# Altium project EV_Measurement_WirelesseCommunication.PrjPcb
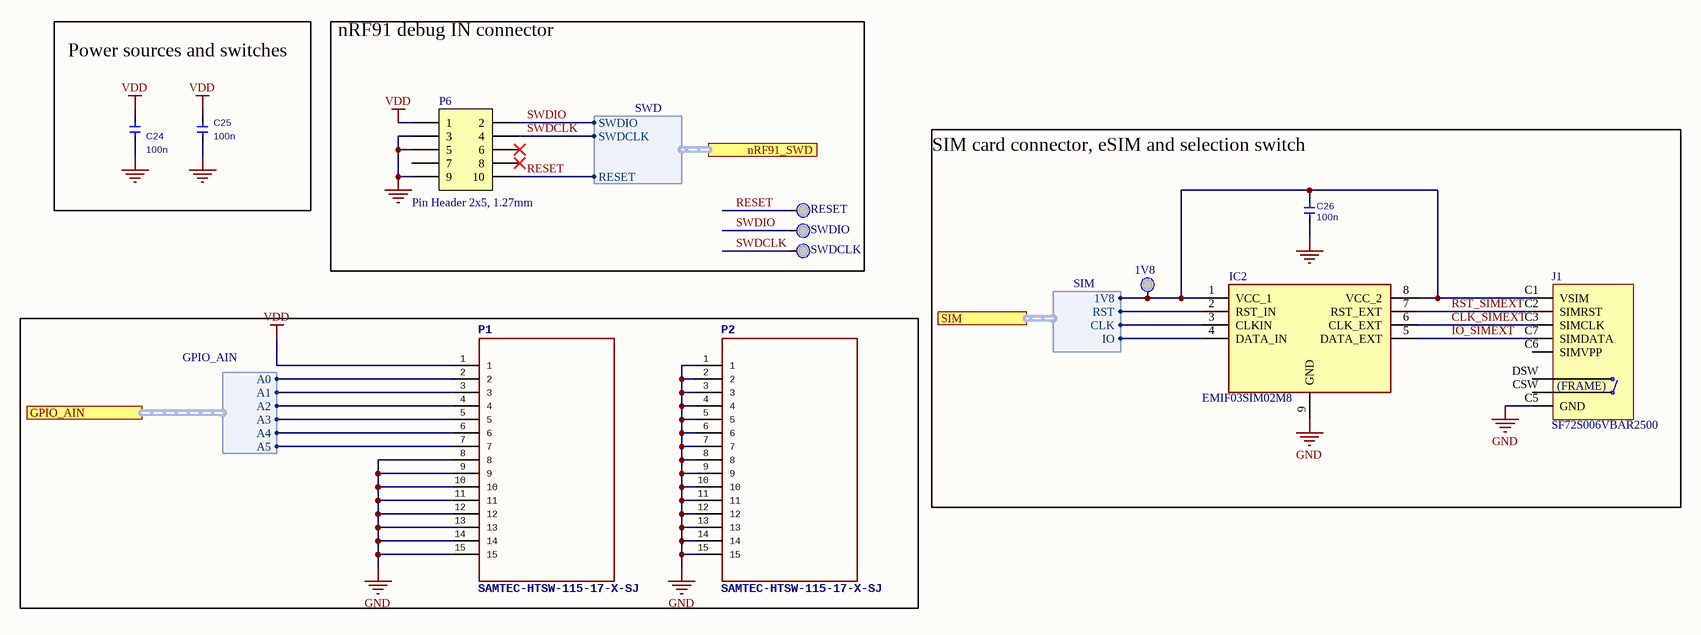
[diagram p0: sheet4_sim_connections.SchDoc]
2 sheets, 30 parts. Net scope: flat (ports and power ports of the same name join across sheets).
Board file: EV_Measurement_Wireless.PcbDoc
Sheets:
  sheet4_sim_connections.SchDoc
  sheet2_nRF9160.SchDoc

## Sheet sheet4_sim_connections.SchDoc
size A3; Author: Mauri Shadi; CompanyName: BFH; DrawnBy: Mauri Shadi; SheetNumber: 1; SheetTotal: 2

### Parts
1V8  TESTPOINT_Black_Small  [Testpoint_Black_Small]  (value not drawn)
C24  100n  [0603(1608)C]
C25  100n  [0603(1608)C]
C26  100n  [0603(1608)C]
IC2  EMIF03SIM02M8  [SON40P150X170X60-9N-D]
J1  SF72S006VBAR2500  [SF72S006VBAR2500]
P1  SAMTEC-HTSW-115-17-X-SJ  [SAMTEC-HTSW-115-17-X-S]
P2  SAMTEC-HTSW-115-17-X-SJ  [SAMTEC-HTSW-115-17-X-S]
P6  Pin Header 2x5, 1.27mm  [HDR_2x5-SMD-1.27mm-K]
RESET  TESTPOINT_Black_Small  [Testpoint_Black_Small]  (value not drawn)
SWDCLK  TESTPOINT_Black_Small  [Testpoint_Black_Small]  (value not drawn)
SWDIO  TESTPOINT_Black_Small  [Testpoint_Black_Small]  (value not drawn)

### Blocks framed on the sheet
Power sources and switches: C24 C25
nRF91 debug IN connector: P6 RESET SWDCLK SWDIO
SIM card connector, eSIM and selection switch: 1V8 C26 IC2 J1

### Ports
GPIO_AIN (harness GPIO_AIN, see sheet2_nRF9160[7C]), nRF91_SWD (harness SWD, see sheet2_nRF9160[7D]), SIM (harness SIM, see sheet2_nRF9160[7C])

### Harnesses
SWD: SWDIO, SWDCLK, RESET
GPIO_AIN: A0, A1, A2, A3, A4, A5
SIM: CLK, IO, 1V8, RST

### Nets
GND: C24.2 C25.1 C26.1 IC2.9(GND) J1.0(GND) J1.C5(GND) P1.8 P1.9 P1.10 P1.11 P1.12 P1.13 P1.14 P1.15 P2.1 P2.2 P2.3 P2.4 P2.5 P2.6 P2.7 P2.8 P2.9 P2.10 P2.11 P2.12 P2.13 P2.14 P2.15 P6.3 P6.5 P6.9
VDD: C24.1 C25.2 P1.1 P6.1  [project net VDD_GPIO]
AIN0: P1.2 ; port GPIO_AIN.A0
AIN1: P1.3 ; port GPIO_AIN.A1
AIN2: P1.4 ; port GPIO_AIN.A2
AIN3: P1.5 ; port GPIO_AIN.A3
AIN4: P1.6 ; port GPIO_AIN.A4
AIN5: P1.7 ; port GPIO_AIN.A5
CLK_SIMEXT: IC2.6(CLK_EXT) J1.C3(SIMCLK)
IO_SIMEXT: IC2.5(DATA_EXT) J1.C7(SIMDATA)
RESET: P6.10 RESET.1 ; port nRF91_SWD.RESET
RST_SIMEXT: IC2.7(RST_EXT) J1.C2(SIMRST)
SIM_1V8: 1V8.1 C26.2 IC2.1(VCC_1) IC2.8(VCC_2) J1.C1(VSIM) ; port SIM.1V8
SIM_CLK: IC2.3(CLKIN) ; port SIM.CLK
SIM_IO: IC2.4(DATA_IN) ; port SIM.IO
SIM_RST: IC2.2(RST_IN) ; port SIM.RST
SWDCLK: P6.4 SWDCLK.1 ; port nRF91_SWD.SWDCLK
SWDIO: P6.2 SWDIO.1 ; port nRF91_SWD.SWDIO

Not connected (* = marked no-connect by the designer): J1 C6(SIMVPP) CSW DSW; P6 6* 7 8*

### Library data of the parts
1V8 RESET SWDCLK SWDIO = TESTPOINT_Black_Small: PCB Test Point, Black, Through Hole Mount, 3.2 mm, Phosphor Bronze; Manufacturer: MULTICOMP; Manufacturer P/N: TEST-1(R)
C24 C25 = C0603_5_100n_25V: Cer Chip Capacitor / 100n/ +-5%/ 25V; Manufacturer Part Number: CC0603KRX7R8BB104; Manufacturer 1: Yageo; Special Value 1: +-5%; Capacitance: 100nF; Tolerance: 10%; Dielectric: X7R
C26 = C0603_5_100n_25V: Cer Chip Capacitor / 100n/ +-5%/ 25V; Manufacturer 1: Yageo; Manufacturer Part Number: CC0603KRX7R8BB104; Special Value 1: +-5%; Capacitance: 100nF; Tolerance: 10%; Dielectric: X7R
IC2 = EMIF03SIM02M8: Integrated Circuit; Manufacturer_Name: STMicroelectronics
J1 = SF72S006VBAR2500: n 8 (6 + 2) Position Card Connector NANO SIM Surface Mount, Right Angle Gold; Manufacturer: JAE Electronics; Part number IPS: 00000009956; Note: N.A.; Pad Count: 8
P6 = Pin Header 2x5 SMD, 1.27mm, KS: Pin Header 2x5, 1.27mm (50mil), SMD, Keying Shroud; Manufacturer: W-CON; Manufacturer Part Number: 3132-10MS0BK00R1; Part number IPS: 00000009968; Note: N.A.; Artikkelnr Noca: 55010009; Pad Count: 10

## Sheet sheet2_nRF9160.SchDoc
size A3; SheetNumber: 2; SheetTotal: 2
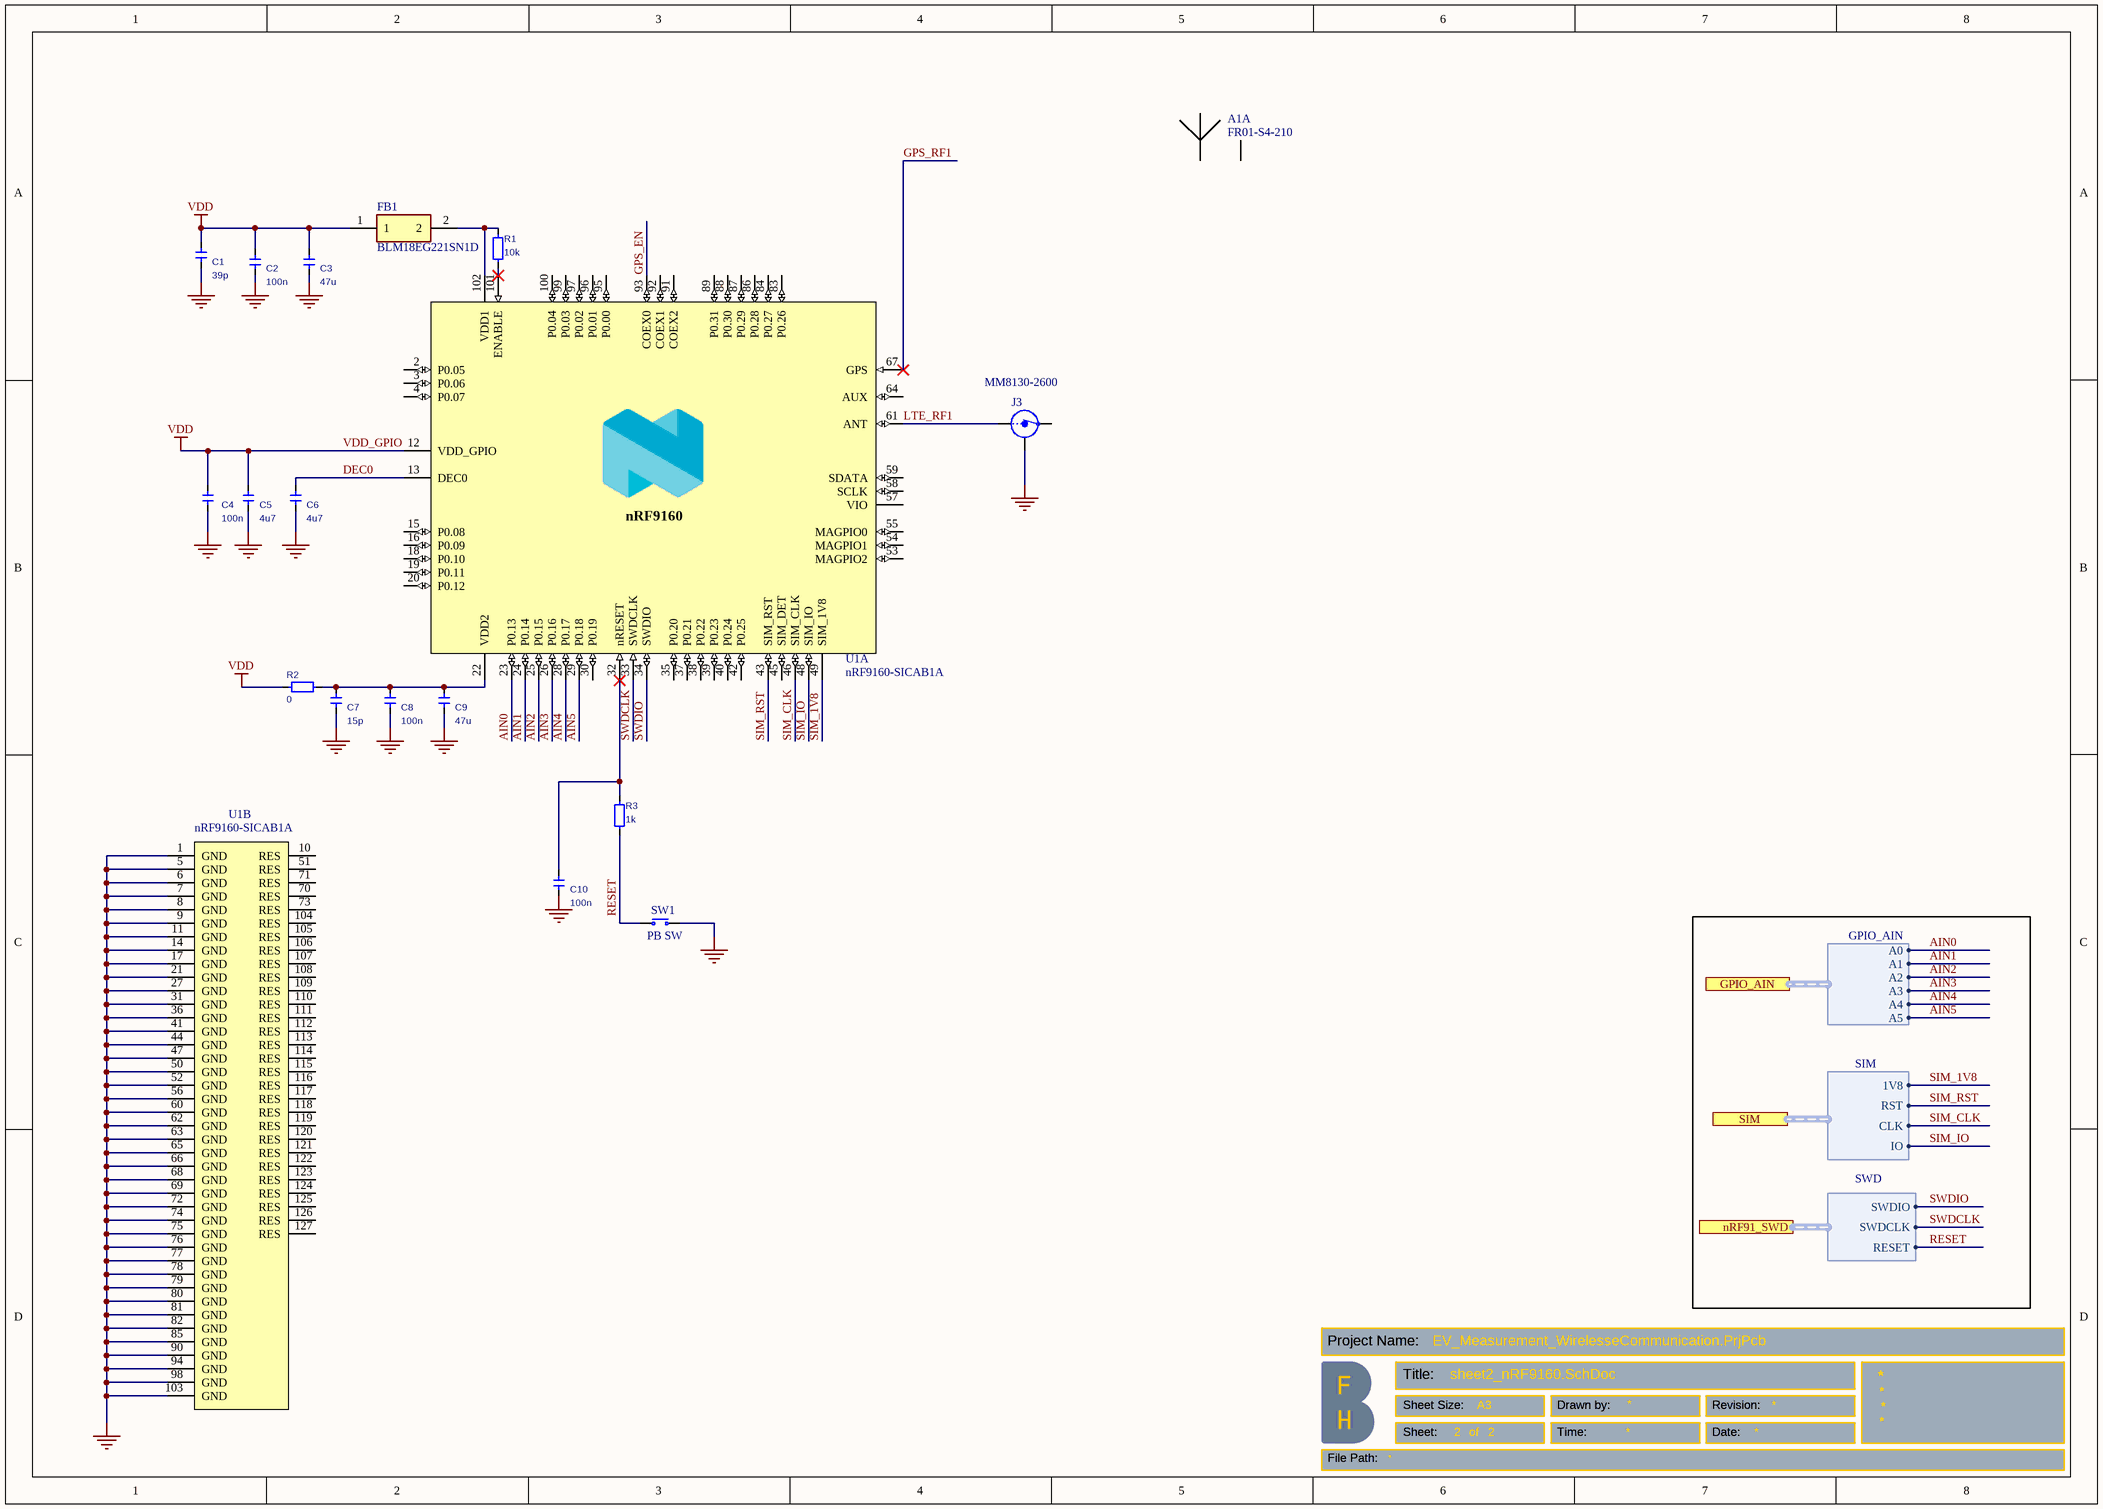
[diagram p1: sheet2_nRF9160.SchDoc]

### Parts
A1  FR01-S4-210  [FR01-S4-210_DF]  (part A of 2)
C1  39p  [0603(1608)C]
C2  100n  [0603(1608)C]
C3  47u  [1206(3216)C]
C4  100n  [0603(1608)C]
C5  4u7  [0603(1608)C]
C6  4u7  [0603(1608)C]
C7  15p  [0603(1608)C]
C8  100n  [0603(1608)C]
C9  47u  [1206(3216)C]
C10  100n  [0603(1608)C]
FB1  BLM18EG221SN1D  [BLM18SP221SN1B]
J3  MM8130-2600  [COAXIAL-SWF]
R1  10k  [0603(1608)]
R2  0  [0603(1608)]
R3  1k  [0603(1608)]
SW1  PB SW  [Switch-PB-6.2x6.3mm-SMD]
U1  nRF9160-SICAB1A  [LGA50P1600X1050X104-161N]  (parts A,B of 2)

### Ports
GPIO_AIN (harness GPIO_AIN, see sheet4_sim_connections[1B]), nRF91_SWD (harness SWD, see sheet4_sim_connections[3A]), SIM (harness SIM, see sheet4_sim_connections[4A])

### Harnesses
GPIO_AIN: A0, A1, A2, A3, A4, A5
SIM: 1V8, RST, CLK, IO
SWD: SWDIO, SWDCLK, RESET

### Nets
GND: C1.2 C2.2 C3.2 C4.2 C5.2 C6.2 C7.2 C8.2 C9.2 C10.2 J3.2(Shield) SW1.1(N.O) U1.1(GND) U1.5(GND) U1.6(GND) U1.7(GND) U1.8(GND) U1.9(GND) U1.11(GND) U1.14(GND) U1.17(GND) U1.21(GND) U1.27(GND) U1.31(GND) U1.36(GND) U1.41(GND) U1.44(GND) U1.47(GND) U1.50(GND) U1.52(GND) U1.56(GND) U1.60(GND) U1.62(GND) U1.63(GND) U1.65(GND) U1.66(GND) U1.68(GND) U1.69(GND) U1.72(GND) U1.74(GND) U1.75(GND) U1.76(GND) U1.77(GND) U1.78(GND) U1.79(GND) U1.80(GND) U1.81(GND) U1.82(GND) U1.85(GND) U1.90(GND) U1.94(GND) U1.98(GND) U1.103(GND)
VDD_GPIO: C1.1 C2.1 C3.1 C4.1 C5.1 FB1.1 R2.1 U1.12(VDD_GPIO)  [also labelled VDD]
AIN0: U1.23(P0.13) ; port GPIO_AIN.A0
AIN1: U1.24(P0.14) ; port GPIO_AIN.A1
AIN2: U1.25(P0.15) ; port GPIO_AIN.A2
AIN3: U1.26(P0.16) ; port GPIO_AIN.A3
AIN4: U1.28(P0.17) ; port GPIO_AIN.A4
AIN5: U1.29(P0.18) ; port GPIO_AIN.A5
DEC0: C6.1 U1.13(DEC0)
GPS_EN: U1.93(COEX0)
GPS_RF1: U1.67(GPS)
LTE_RF1: J3.1(IN) U1.61(ANT)
RESET: R3.1 SW1.2(COM) ; port nRF91_SWD.RESET
SIM_1V8: U1.49(SIM_1V8) ; port SIM.1V8
SIM_CLK: U1.46(SIM_CLK) ; port SIM.CLK
SIM_IO: U1.48(SIM_IO) ; port SIM.IO
SIM_RST: U1.43(SIM_RST) ; port SIM.RST
SWDCLK: U1.33(SWDCLK) ; port nRF91_SWD.SWDCLK
SWDIO: U1.34(SWDIO) ; port nRF91_SWD.SWDIO
NetC7_1: C7.1 C8.1 C9.1 R2.2 U1.22(VDD2)
NetC10_1: C10.1 R3.2 U1.32(nRESET)
NetFB1_2: FB1.2 R1.1 U1.102(VDD1)
NetR1_2: R1.2 U1.101(ENABLE)

Not connected (* = marked no-connect by the designer): A1 1(Feed_A) 2(Tuning_A); J3 3(OUT); U1 2(P0.05) 3(P0.06) 4(P0.07) 10(RES) 15(P0.08) 16(P0.09) 18(P0.10) 19(P0.11) 20(P0.12) 30(P0.19) 35(P0.20) 37(P0.21) 38(P0.22) 39(P0.23) 40(P0.24) 42(P0.25) 45(SIM_DET) 51(RES) 53(MAGPIO2) 54(MAGPIO1) 55(MAGPIO0) 57(VIO) 58(SCLK) 59(SDATA) 64(AUX) 70(RES) 71(RES) 73(RES) 83(P0.26) 84(P0.27) 86(P0.28) 87(P0.29) 88(P0.30) 89(P0.31) 91(COEX2) 92(COEX1) 95(P0.00) 96(P0.01) 97(P0.02) 99(P0.03) 100(P0.04) 104(RES) 105(RES) 106(RES) 107(RES) 108(RES) 109(RES) 110(RES) 111(RES) 112(RES) 113(RES) 114(RES) 115(RES) 116(RES) 117(RES) 118(RES) 119(RES) 120(RES) 121(RES) 122(RES) 123(RES) 124(RES) 125(RES) 126(RES) 127(RES)

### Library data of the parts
A1 = FR01-S4-210-D: Mobile IoT LTE Multi-Band Antenna; Manufacturer: Fractus Antennas; Part number IPS: 80000001819; Note: N.A.; Pad Count: 5
C1 = C0603_1_39p_50V: Cer Chip Capacitor / 15p/ +-1%/ 50V; Manufacturer: Murata; Manufacturer P/N: GCM1885C1H390FA16J; Special Value 1: +-1%
C2 C4 C8 C10 = C0603_5_100n_25V: as C24 on sheet sheet4_sim_connections
C3 C9 = C1206_7_47u_6.3V: Cer Chip Capacitor / 47u/ +-10%/ 6.3V; Manufacturer Part Number: CL31A476MQHNNNE; Manufacturer 1: Samsung; Special Value 1: +-20%; Material: Ceramic; Capacitance: 47uF; Tolerance: 20%; Dielectric: X5R
C5 C6 = C0603_6_4u7_25V: Cer Chip Capacitor / 4u7/ +-10%/ 25V; Manufacturer Part Number: CL10A475MA8NQNC; Manufacturer 1: Samsung; Special Value 1: +-10%; Capacitance: 4.7uF; Tolerance: 20%; Dielectric: X5R
C7 = C0603_1_39p_50V: Cer Chip Capacitor / 15p/ +-1%/ 50V; Manufacturer: Murata; Manufacturer P/N: GCM1885C1H390FA16J; Value: 39p; Special Value 1: +-1%
FB1 = BLM18EG221SN1D: Ferrite Bead; Manufacturer_Name: Murata Electronics
J3 = MM8130-2600: Coaxial Connector with Switch; Manufacturer: Murata; Part number IPS: 00000009955; Note: N.A.; Artikkelnr Noca: 55029011; Pad Count: 3
R1 = R0603_4_10k: Chip Resistor / 10k/ 1% / 50V / 100mW / 0603(1608); Manufacturer Part Number: RR0816P-103-D; Manufacturer 1: Susumu; Resistance: 10kR; Tolerance: 0.5%; Power Rating: 63mW; Voltage Rating: 75V; Temperature Coefficient: 25ppm/°C
R2 = R0603_0_0E: Chip Resistor / 0E / 1% / 50V / 100mW / 0603(1608); Manufacturer Part Number: ERJ-3GEY0R00V; Manufacturer 1: Panasonic; Resistance: 0mR; Voltage Rating: 75V; Tolerance: 0%; Temperature Coefficient: 600ppm/°C
R3 = R0603_3_1k: Chip Resistor / 1k/ 1% / 50V / 100mW / 0603(1608); Manufacturer: Panasonic; Manufacturer Part Number: ERA-8AEB102V; Resistance: 1kR; Power Rating: 250mW; Tolerance: 0.1%; Voltage Rating: 150V; Temperature Coefficient: 25ppm/°C
SW1 = Switch-PB-6.2x6.3mm-SMD: Tactile Switch, SPNO, SMD, 160gf, 6.2x6.3x2.5mm; Manufacturer: Dailywell; Manufacturer Part Number: TS604VM1-025BR-R; Part number IPS: 00000007812; Note: N.A.; Artikkelnr Noca: 50019106; Pad Count: 4
U1 = nRF9160-SICAB1A: Low power System-in-Package with integrated LTE-M/NB-IoT modem and GPS; Manufacturer: Nordic Semiconductor; Part number IPS: 80000002329; Note: N.A.; Pad Count: 161

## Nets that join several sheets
GND: sheet4_sim_connections (32 pins), sheet2_nRF9160 (53 pins)
VDD_GPIO: sheet4_sim_connections (C24.1 C25.2 P1.1 P6.1), sheet2_nRF9160 (8 pins)
AIN0: sheet4_sim_connections (P1.2), sheet2_nRF9160 (U1.23)
AIN1: sheet4_sim_connections (P1.3), sheet2_nRF9160 (U1.24)
AIN2: sheet4_sim_connections (P1.4), sheet2_nRF9160 (U1.25)
AIN3: sheet4_sim_connections (P1.5), sheet2_nRF9160 (U1.26)
AIN4: sheet4_sim_connections (P1.6), sheet2_nRF9160 (U1.28)
AIN5: sheet4_sim_connections (P1.7), sheet2_nRF9160 (U1.29)
RESET: sheet4_sim_connections (P6.10 RESET.1), sheet2_nRF9160 (R3.1 SW1.2)
SIM_1V8: sheet4_sim_connections (5 pins), sheet2_nRF9160 (U1.49)
SIM_CLK: sheet4_sim_connections (IC2.3), sheet2_nRF9160 (U1.46)
SIM_IO: sheet4_sim_connections (IC2.4), sheet2_nRF9160 (U1.48)
SIM_RST: sheet4_sim_connections (IC2.2), sheet2_nRF9160 (U1.43)
SWDCLK: sheet4_sim_connections (P6.4 SWDCLK.1), sheet2_nRF9160 (U1.33)
SWDIO: sheet4_sim_connections (P6.2 SWDIO.1), sheet2_nRF9160 (U1.34)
